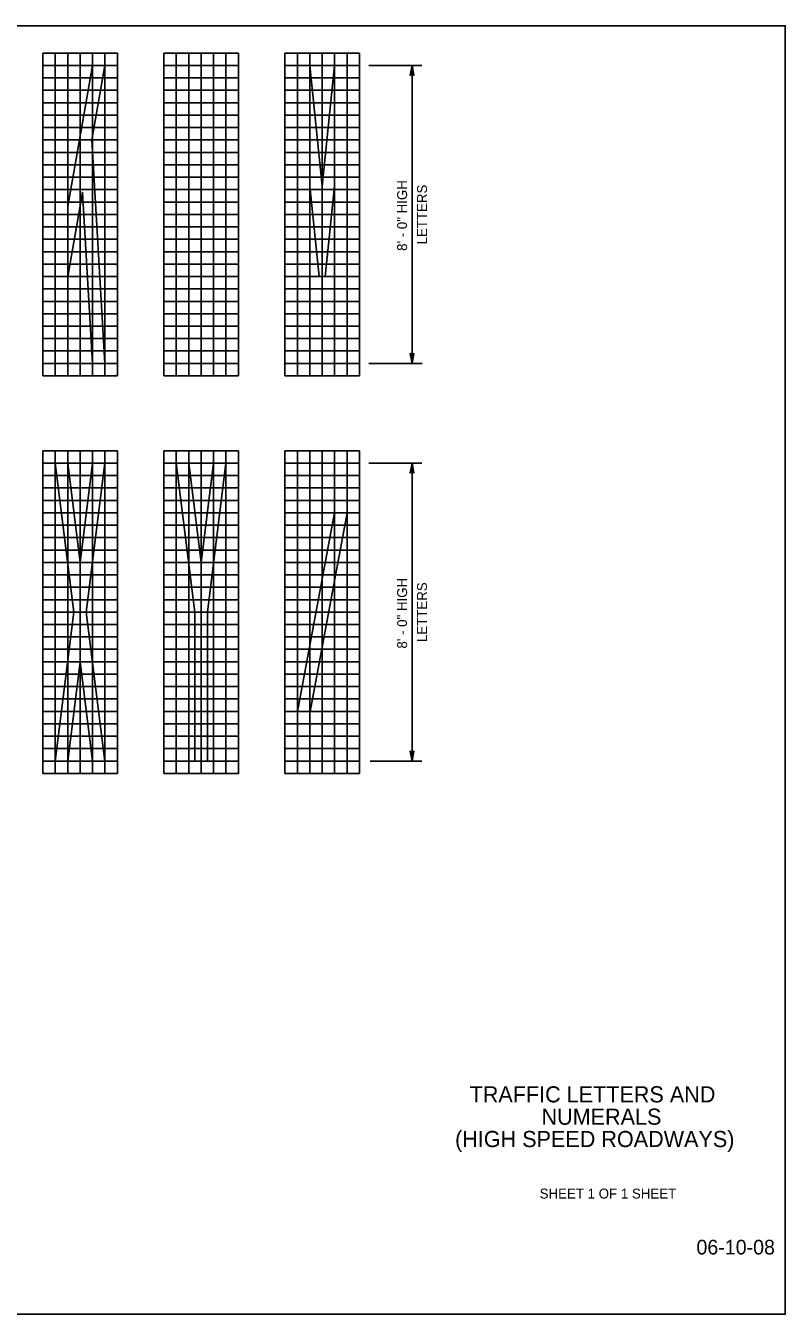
# Model space of a CAD drawing. Extents: x 99862 to 103151, y 100000 to 102076.
# Drawn here: x 101927 to 103151, y 100000 to 102076 of the extents above; entities that cross this region are included whole.
import ezdxf

# ---------------------------------------------------------------- set-up
doc = ezdxf.new("R2010")
doc.units = 0
for name, color, linetype in [('Level 1', 7, 'Continuous'), ('Level 15', 7, 'Continuous'), ('Level 20', 7, 'Continuous'), ('Level 4', 7, 'Continuous'), ('Level 60', 7, 'Continuous'), ('Level 62', 7, 'Continuous')]:
    doc.layers.add(name, color=color, linetype=linetype)

msp = doc.modelspace()

# ---------------------------------------------------------------- linework, layer by layer
at = {"layer": 'Level 1'}
msp.add_lwpolyline([(99862, 99999.5), (103151, 99999.5), (103151, 102075.5), (99862, 102075.5)], close=True, dxfattribs=at)
at = {"layer": 'Level 15'}
for p, q in [((102480.3, 102011.5), (102565.8, 102011.5)), ((102549.8, 102011.5), (102549.8, 101531.6)), ((102480, 101531.5), (102566, 101531.5)), ((102480.3, 101370.8), (102565.8, 101370.8)), ((102549.8, 101370.8), (102549.8, 100890.8)), ((102482.5, 100890.8), (102565.8, 100890.8))]:
    msp.add_line(p, q, dxfattribs=at)
for points in [[(101975, 101671.5), (101975, 101531.5), (101995, 101531.5), (101995, 101671.5), (102018.9, 101806.9), (102035, 101531.5), (102055, 101531.5), (102033.8, 101891.5), (102055, 102011.5), (102035, 102011.5), (102013.9, 101891.5), (101995, 101784.8), (101995, 102011.5), (101975, 102011.5)], [(102190, 101611.5), (102190, 102011.5), (102170, 102011.5), (102170, 101531.5), (102187.5, 101531.5), (102190, 101531.5), (102250, 101531.5), (102250, 101611.5)], [(102425, 101817.2), (102425, 101531.5), (102445, 101531.5), (102445, 102011.5), (102425, 102011.5), (102405, 101817.2), (102385, 102011.5), (102365, 102011.5), (102365, 101531.5), (102385, 101531.5), (102385, 101817.2), (102400, 101671.5), (102410, 101671.5)], [(102549.8, 102011.5), (102546.7, 101995.8), (102549.8, 101996.5), (102552.9, 101995.8)], [(102549.8, 101531.6), (102546.7, 101547.3), (102549.8, 101546.6), (102552.9, 101547.3)], [(102005, 101130.8), (101975, 100890.8), (101995, 100890.8), (102015, 101050.8), (102035, 100890.8), (102055, 100890.8), (102025, 101130.8), (102055, 101370.8), (102035, 101370.8), (102015, 101210.8), (101995, 101370.8), (101975, 101370.8)], [(102220, 101130.8), (102250, 101370.8), (102230, 101370.8), (102210, 101210.8), (102190, 101370.8), (102170, 101370.8), (102200, 101130.8), (102200, 100890.8), (102220, 100890.8)], [(102385.4, 100970.8), (102445, 101290.8), (102445, 101370.8), (102365, 101370.8), (102365, 101290.8), (102424.7, 101290.8), (102365, 100970.8), (102365, 100890.8), (102445, 100890.8), (102445, 100970.8)], [(102549.8, 101370.8), (102546.7, 101355), (102549.8, 101355.8), (102552.9, 101355)], [(102549.8, 100890.8), (102546.7, 100906.5), (102549.8, 100905.8), (102552.9, 100906.5)]]:
    msp.add_lwpolyline(points, close=True, dxfattribs=at)
at = {"layer": 'Level 4'}
for p, q in [((101955, 102031.5), (101955, 101511.5)), ((101955, 102031.5), (102075, 102031.5)), ((101975, 102031.5), (101975, 101511.5)), ((101995, 102031.5), (101995, 101511.5)), ((102015, 102031.5), (102015, 101511.5)), ((102035, 102031.5), (102035, 101511.5)), ((102055, 102031.5), (102055, 101511.5)), ((102075, 102031.5), (102075, 101511.5)), ((102150, 102031.5), (102150, 101511.5)), ((102150, 102031.5), (102270, 102031.5)), ((102170, 102031.5), (102170, 101511.5)), ((102190, 102031.5), (102190, 101511.5)), ((102210, 102031.5), (102210, 101511.5)), ((102230, 102031.5), (102230, 101511.5)), ((102250, 102031.5), (102250, 101511.5)), ((102270, 102031.5), (102270, 101511.5)), ((102345, 102031.5), (102345, 101511.5)), ((102345, 102031.5), (102465, 102031.5)), ((102365, 102031.5), (102365, 101511.5)), ((102385, 102031.5), (102385, 101511.5)), ((102405, 102031.5), (102405, 101511.5)), ((102425, 102031.5), (102425, 101511.5)), ((102445, 102031.5), (102445, 101511.5)), ((102465, 102031.5), (102465, 101511.5)), ((101955, 102011.5), (102075, 102011.5)), ((102150, 102011.5), (102270, 102011.5)), ((102345, 102011.5), (102465, 102011.5)), ((101955, 101991.5), (102075, 101991.5)), ((102150, 101991.5), (102270, 101991.5)), ((102345, 101991.5), (102465, 101991.5)), ((101955, 101971.5), (102075, 101971.5)), ((102150, 101971.5), (102270, 101971.5)), ((102345, 101971.5), (102465, 101971.5)), ((101955, 101951.5), (102075, 101951.5)), ((102150, 101951.5), (102270, 101951.5)), ((102345, 101951.5), (102465, 101951.5)), ((101955, 101931.5), (102075, 101931.5)), ((101955, 101911.5), (102075, 101911.5)), ((102150, 101931.5), (102270, 101931.5)), ((102150, 101911.5), (102270, 101911.5)), ((102345, 101931.5), (102465, 101931.5)), ((102345, 101911.5), (102465, 101911.5)), ((101955, 101891.5), (102075, 101891.5)), ((102150, 101891.5), (102270, 101891.5)), ((102345, 101891.5), (102465, 101891.5)), ((101955, 101871.5), (102075, 101871.5)), ((102150, 101871.5), (102270, 101871.5)), ((102345, 101871.5), (102465, 101871.5)), ((101955, 101851.5), (102075, 101851.5)), ((102150, 101851.5), (102270, 101851.5)), ((102345, 101851.5), (102465, 101851.5)), ((101955, 101831.5), (102075, 101831.5)), ((102150, 101831.5), (102270, 101831.5)), ((102345, 101831.5), (102465, 101831.5)), ((101955, 101811.5), (102075, 101811.5)), ((102150, 101811.5), (102270, 101811.5)), ((102345, 101811.5), (102465, 101811.5)), ((101955, 101791.5), (102075, 101791.5)), ((102150, 101791.5), (102270, 101791.5)), ((102345, 101791.5), (102465, 101791.5)), ((101955, 101771.5), (102075, 101771.5)), ((102150, 101771.5), (102270, 101771.5)), ((102345, 101771.5), (102465, 101771.5)), ((101955, 101751.5), (102075, 101751.5)), ((102150, 101751.5), (102270, 101751.5)), ((102345, 101751.5), (102465, 101751.5)), ((101955, 101731.5), (102075, 101731.5)), ((102150, 101731.5), (102270, 101731.5)), ((102345, 101731.5), (102465, 101731.5)), ((101955, 101711.5), (102075, 101711.5)), ((102150, 101711.5), (102270, 101711.5)), ((102345, 101711.5), (102465, 101711.5)), ((101955, 101691.5), (102075, 101691.5)), ((102150, 101691.5), (102270, 101691.5)), ((102345, 101691.5), (102465, 101691.5)), ((101955, 101671.5), (102075, 101671.5)), ((102150, 101671.5), (102270, 101671.5)), ((102345, 101671.5), (102465, 101671.5)), ((101955, 101651.5), (102075, 101651.5)), ((102150, 101651.5), (102270, 101651.5)), ((102345, 101651.5), (102465, 101651.5)), ((101955, 101631.5), (102075, 101631.5)), ((102150, 101631.5), (102270, 101631.5)), ((102345, 101631.5), (102465, 101631.5)), ((101955, 101611.5), (102075, 101611.5)), ((102150, 101611.5), (102270, 101611.5)), ((102345, 101611.5), (102465, 101611.5)), ((101955, 101591.5), (102075, 101591.5)), ((102150, 101591.5), (102270, 101591.5)), ((102345, 101591.5), (102465, 101591.5)), ((101955, 101571.5), (102075, 101571.5)), ((102150, 101571.5), (102270, 101571.5)), ((102345, 101571.5), (102465, 101571.5)), ((101955, 101551.5), (102075, 101551.5)), ((102150, 101551.5), (102270, 101551.5)), ((102345, 101551.5), (102465, 101551.5)), ((101955, 101531.5), (102075, 101531.5)), ((102150, 101531.5), (102270, 101531.5)), ((102345, 101531.5), (102465, 101531.5)), ((101955, 101511.5), (102075, 101511.5)), ((102150, 101511.5), (102270, 101511.5)), ((102345, 101511.5), (102465, 101511.5)), ((101955, 101390.8), (101955, 100870.8)), ((101955, 101390.8), (102075, 101390.8)), ((101975, 101390.8), (101975, 100870.8)), ((101995, 101390.8), (101995, 100870.8)), ((102015, 101390.8), (102015, 100870.8)), ((102035, 101390.8), (102035, 100870.8)), ((102055, 101390.8), (102055, 100870.8)), ((102075, 101390.8), (102075, 100870.8)), ((102150, 101390.8), (102150, 100870.8)), ((102150, 101390.8), (102270, 101390.8)), ((102170, 101390.8), (102170, 100870.8)), ((102190, 101390.8), (102190, 100870.8)), ((102210, 101390.8), (102210, 100870.8)), ((102230, 101390.8), (102230, 100870.8)), ((102250, 101390.8), (102250, 100870.8)), ((102270, 101390.8), (102270, 100870.8)), ((102345, 101390.8), (102345, 100870.8)), ((102345, 101390.8), (102465, 101390.8)), ((102365, 101390.8), (102365, 100870.8)), ((102385, 101390.8), (102385, 100870.8)), ((102405, 101390.8), (102405, 100870.8)), ((102425, 101390.8), (102425, 100870.8)), ((102445, 101390.8), (102445, 100870.8)), ((102465, 101390.8), (102465, 100870.8)), ((101955, 101370.8), (102075, 101370.8)), ((101955, 101350.8), (102075, 101350.8)), ((102150, 101370.8), (102270, 101370.8)), ((102150, 101350.8), (102270, 101350.8)), ((102345, 101370.8), (102465, 101370.8)), ((102345, 101350.8), (102465, 101350.8)), ((101955, 101330.8), (102075, 101330.8)), ((102150, 101330.8), (102270, 101330.8)), ((102345, 101330.8), (102465, 101330.8)), ((101955, 101310.8), (102075, 101310.8)), ((102150, 101310.8), (102270, 101310.8)), ((102345, 101310.8), (102465, 101310.8)), ((101955, 101290.8), (102075, 101290.8)), ((102150, 101290.8), (102270, 101290.8)), ((102345, 101290.8), (102465, 101290.8)), ((101955, 101270.8), (102075, 101270.8)), ((102150, 101270.8), (102270, 101270.8)), ((102345, 101270.8), (102465, 101270.8)), ((101955, 101250.8), (102075, 101250.8)), ((102150, 101250.8), (102270, 101250.8)), ((102345, 101250.8), (102465, 101250.8)), ((101955, 101230.8), (102075, 101230.8)), ((102150, 101230.8), (102270, 101230.8)), ((102345, 101230.8), (102465, 101230.8)), ((101955, 101210.8), (102075, 101210.8)), ((102150, 101210.8), (102270, 101210.8)), ((102345, 101210.8), (102465, 101210.8)), ((101955, 101190.8), (102075, 101190.8)), ((102150, 101190.8), (102270, 101190.8)), ((102345, 101190.8), (102465, 101190.8)), ((101955, 101170.8), (102075, 101170.8)), ((102150, 101170.8), (102270, 101170.8)), ((102345, 101170.8), (102465, 101170.8)), ((101955, 101150.8), (102075, 101150.8)), ((102150, 101150.8), (102270, 101150.8)), ((102345, 101150.8), (102465, 101150.8)), ((101955, 101130.8), (102075, 101130.8)), ((102150, 101130.8), (102270, 101130.8)), ((102345, 101130.8), (102465, 101130.8)), ((101955, 101110.8), (102075, 101110.8)), ((102150, 101110.8), (102270, 101110.8)), ((102345, 101110.8), (102465, 101110.8)), ((101955, 101090.8), (102075, 101090.8)), ((102150, 101090.8), (102270, 101090.8)), ((102345, 101090.8), (102465, 101090.8)), ((101955, 101070.8), (102075, 101070.8)), ((102150, 101070.8), (102270, 101070.8)), ((102345, 101070.8), (102465, 101070.8)), ((101955, 101050.8), (102075, 101050.8)), ((102150, 101050.8), (102270, 101050.8)), ((102345, 101050.8), (102465, 101050.8)), ((101955, 101030.8), (102075, 101030.8)), ((102150, 101030.8), (102270, 101030.8)), ((102345, 101030.8), (102465, 101030.8)), ((101955, 101010.8), (102075, 101010.8)), ((102150, 101010.8), (102270, 101010.8)), ((102345, 101010.8), (102465, 101010.8)), ((101955, 100990.8), (102075, 100990.8)), ((102150, 100990.8), (102270, 100990.8)), ((102345, 100990.8), (102465, 100990.8)), ((101955, 100970.8), (102075, 100970.8)), ((102150, 100970.8), (102270, 100970.8)), ((102345, 100970.8), (102465, 100970.8)), ((101955, 100950.8), (102075, 100950.8)), ((102150, 100950.8), (102270, 100950.8)), ((102345, 100950.8), (102465, 100950.8)), ((101955, 100930.8), (102075, 100930.8)), ((102150, 100930.8), (102270, 100930.8)), ((102345, 100930.8), (102465, 100930.8)), ((101955, 100910.8), (102075, 100910.8)), ((102150, 100910.8), (102270, 100910.8)), ((102345, 100910.8), (102465, 100910.8)), ((101955, 100890.8), (102075, 100890.8)), ((102150, 100890.8), (102270, 100890.8)), ((102345, 100890.8), (102465, 100890.8)), ((101955, 100870.8), (102075, 100870.8)), ((102150, 100870.8), (102270, 100870.8)), ((102345, 100870.8), (102465, 100870.8))]:
    msp.add_line(p, q, dxfattribs=at)
at = {"layer": 'Level 60'}
msp.add_line((103151, 102075.5), (103151, 102075.5), dxfattribs=at)

# ---------------------------------------------------------------- texts
at = {"layer": 'Level 1'}
msp.add_text('06-10-08', height=23.62, dxfattribs=at).set_placement((103008, 100095.8))
at = {"layer": 'Level 20'}
for s, p in [('8\' - 0" HIGH', (102541.8, 101712.8)), ('LETTERS', (102573.8, 101723.2)), ('8\' - 0" HIGH', (102541.8, 101072)), ('LETTERS', (102573.8, 101082.5))]:
    msp.add_text(s, height=16, rotation=90, dxfattribs=at).set_placement(p)
at = {"layer": 'Level 62'}
for s, height, p in [('TRAFFIC LETTERS AND', 26, (102642.5, 100340.8)), (' NUMERALS ', 26, (102748.7, 100304.8)), (' (HIGH SPEED ROADWAYS)', 26, (102609.4, 100268.8)), ('SHEET 1 OF 1 SHEET', 16, (102755.4, 100185.9))]:
    msp.add_text(s, height=height, dxfattribs=at).set_placement(p)

doc.saveas('drawing.dxf')
